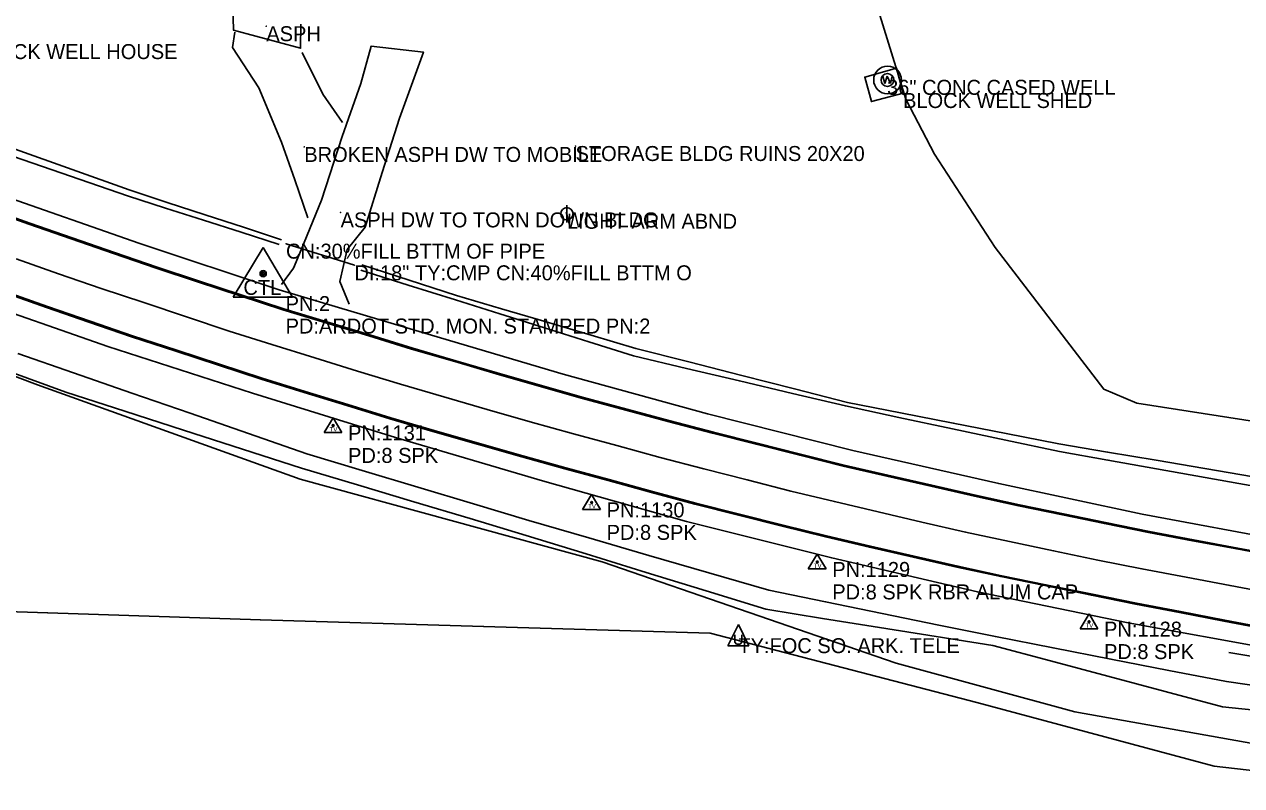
# Model space of a CAD drawing. Extents: x 878399 to 889864, y 1564003 to 1567413.
# Drawn here: x 886065.8 to 886472.5, y 1564453.2 to 1564707.5 of the extents above; entities that cross this region are included whole.
import ezdxf

# ---------------------------------------------------------------- set-up
doc = ezdxf.new("R2010")
doc.units = 0
for name, color, linetype in [('S_BUILDING', 7, 'Continuous'), ('S_BUILDING_ANNOT', 7, 'Continuous'), ('S_DITCHLINE', 7, 'Continuous'), ('S_DRG_PT_SYM', 7, 'Continuous'), ('S_DRIVEWAY', 7, 'Continuous'), ('S_EDGE_BITUMINOUS', 7, 'Continuous'), ('S_EDGE_PAVEMENT', 7, 'Continuous'), ('S_FENCE', 7, 'Continuous'), ('S_FIBER_OPTIC_CABLE', 7, 'Continuous'), ('S_MSC_PT_SYM', 7, 'Continuous'), ('S_PAVEMENT_CROWN', 7, 'Continuous'), ('S_PRIMARY_CTL', 7, 'Continuous'), ('S_PRIMARY_CTL_ANNOT', 7, 'Continuous'), ('S_SECONDARY_CTL', 7, 'Continuous'), ('S_SECONDARY_CTL_ANNOT', 7, 'Continuous'), ('S_SHOULDER', 7, 'Continuous'), ('S_SIDE_DRAIN', 7, 'Continuous'), ('S_SIDE_DRAIN_ANNOT', 7, 'Continuous'), ('S_STR_PT_SYM', 7, 'Continuous'), ('S_SURVEY_TEXT_ANNOT', 7, 'Continuous'), ('S_UTILITY_POLE', 7, 'Continuous'), ('S_UTILITY_POLE_ANNOT', 7, 'Continuous'), ('S_UTL_PT_SYM', 7, 'Continuous'), ('S_WATER_WELL', 7, 'Continuous'), ('S_WATER_WELL_ANNOT', 7, 'Continuous')]:
    doc.layers.add(name, color=color, linetype=linetype)

msp = doc.modelspace()

# ---------------------------------------------------------------- linework, layer by layer
at = {"layer": 'S_BUILDING'}
for p, q in [((886346.55, 1564689.87), (886357.12, 1564692.84)), ((886357.12, 1564692.84), (886359.35, 1564684.57)), ((886348.76, 1564681.74), (886346.55, 1564689.87)), ((886359.35, 1564684.57), (886348.76, 1564681.74))]:
    msp.add_line(p, q, dxfattribs=at)
at = {"layer": 'S_DITCHLINE'}
for points in [[(886151.69, 1564635.57), (886138.96, 1564639.73), (886126.22, 1564643.88), (886113.49, 1564648.04), (886100.75, 1564652.2), (886081.74, 1564659.01), (886062.72, 1564665.83), (886043.71, 1564672.65), (886024.7, 1564679.47), (886007.11, 1564687.39), (885989.52, 1564695.32), (885971.94, 1564703.24), (885954.35, 1564711.17), (885939.66, 1564718.75), (885924.96, 1564726.34), (885905.6, 1564735.73), (885886.23, 1564745.12), (885866.86, 1564754.51), (885847.49, 1564763.9)], [(886150.93, 1564634.01), (886138.26, 1564638.06), (886125.58, 1564642.1), (886112.9, 1564646.14), (886100.22, 1564650.18), (886081.18, 1564656.77), (886062.13, 1564663.36), (886043.09, 1564669.96), (886024.05, 1564676.55), (886006.01, 1564683.98), (885987.98, 1564691.41), (885969.95, 1564698.83), (885951.91, 1564706.26), (885936.25, 1564712.21), (885920.59, 1564718.15), (885901.35, 1564727.33), (885882.11, 1564736.51), (885862.87, 1564745.69), (885843.63, 1564754.86)], [(886476.49, 1564553.26), (886460.26, 1564556.16), (886444.03, 1564559.05), (886427.8, 1564561.95), (886411.56, 1564564.84), (886393.69, 1564568.64), (886375.82, 1564572.44), (886357.95, 1564576.23), (886340.08, 1564580.03), (886322.38, 1564584.21), (886304.67, 1564588.39), (886286.97, 1564592.57), (886269.27, 1564596.75), (886254.4, 1564601.44), (886239.54, 1564606.12), (886224.67, 1564610.81), (886209.8, 1564615.5), (886193.98, 1564620.42), (886178.16, 1564625.35)], [(886476.42, 1564556.37), (886460.17, 1564559.13), (886443.92, 1564561.89), (886427.67, 1564564.66), (886411.42, 1564567.42), (886393.76, 1564570.88), (886376.09, 1564574.34), (886358.43, 1564577.79), (886340.77, 1564581.25), (886323.11, 1564585.76), (886305.44, 1564590.27), (886287.78, 1564594.78), (886270.12, 1564599.29), (886255.14, 1564603.7), (886240.16, 1564608.11), (886225.18, 1564612.52), (886210.2, 1564616.94), (886194.38, 1564622.09), (886178.56, 1564627.24)], [(886481.16, 1564485.98), (886467.4, 1564487.97), (886448.09, 1564491.72), (886428.79, 1564495.48), (886409.48, 1564499.23), (886390.18, 1564502.99), (886371.27, 1564506.86), (886352.36, 1564510.73), (886333.46, 1564514.61), (886314.55, 1564518.48), (886294.5, 1564524.31), (886274.45, 1564530.13), (886254.39, 1564535.95), (886234.34, 1564541.78), (886215.78, 1564547.35), (886197.23, 1564552.92), (886178.67, 1564558.5), (886160.12, 1564564.07), (886140.64, 1564570.83), (886121.16, 1564577.59), (886101.69, 1564584.35), (886082.21, 1564591.11), (886063.62, 1564597.61)], [(886480.05, 1564478.13), (886466.11, 1564479.57), (886446.93, 1564484.67), (886427.74, 1564489.78), (886408.55, 1564494.88), (886389.36, 1564499.99), (886370.4, 1564503.02), (886351.44, 1564506.05), (886332.48, 1564509.08), (886313.52, 1564512.12), (886293.51, 1564518.29), (886273.49, 1564524.46), (886253.48, 1564530.63), (886233.47, 1564536.8), (886214.69, 1564542.42), (886195.9, 1564548.03), (886177.12, 1564553.65), (886158.34, 1564559.27), (886138.67, 1564565.63), (886119, 1564571.99), (886099.33, 1564578.34), (886079.66, 1564584.7), (886061.03, 1564591.49)]]:
    msp.add_lwpolyline(points, dxfattribs=at)
at = {"layer": 'S_DRG_PT_SYM'}
for points in [[(886153.21, 1564634.25), (886153.21, 1564634.3), (886153.21, 1564634.25), (886153.16, 1564634.25), (886153.21, 1564634.25), (886153.21, 1564634.2), (886153.21, 1564634.25), (886153.26, 1564634.25)], [(886176.05, 1564627.02), (886176.05, 1564627.07), (886176.05, 1564627.02), (886176, 1564627.02), (886176.05, 1564627.02), (886176.05, 1564626.97), (886176.05, 1564627.02), (886176.1, 1564627.02)]]:
    msp.add_lwpolyline(points, dxfattribs=at)
at = {"layer": 'S_DRIVEWAY'}
for points in [[(886160.51, 1564642.93), (886156.11, 1564655.57), (886151.7, 1564668.21), (886144.17, 1564686.34), (886135.36, 1564699.78), (886136.06, 1564704.96)], [(886151.65, 1564620.63), (886155.73, 1564626.04), (886158.3, 1564632.14), (886165.07, 1564648.74), (886171.96, 1564670.01), (886178.19, 1564687.72), (886181.69, 1564700.25), (886199.11, 1564698.27), (886191.09, 1564676.16), (886185.35, 1564657.98), (886179.61, 1564639.81), (886173.65, 1564632.28), (886171.15, 1564621.66), (886174.28, 1564614.08)], [(886158.58, 1564698.17), (886165.52, 1564684.23), (886172.07, 1564674.74)]]:
    msp.add_lwpolyline(points, dxfattribs=at)
at = {"layer": 'S_EDGE_BITUMINOUS'}
msp.add_lwpolyline([(886135.38, 1564713.85), (886135.68, 1564705.53), (886158.05, 1564699.54), (886158.15, 1564707.53)], dxfattribs=at)
at = {"layer": 'S_EDGE_PAVEMENT'}
for points in [[(886053.09, 1564645.79), (886067.25, 1564640.82), (886081.41, 1564635.87), (886095.57, 1564630.92), (886109.78, 1564626.1), (886123.61, 1564621.52), (886137.85, 1564616.8), (886137.85, 1564616.8), (886137.85, 1564616.8), (886152.12, 1564612.16), (886166.47, 1564607.79), (886180.82, 1564603.43), (886195.17, 1564599.06), (886209.57, 1564594.85), (886223.37, 1564590.82), (886237.78, 1564586.62), (886252.23, 1564582.58), (886252.23, 1564582.58), (886266.72, 1564578.68), (886281.21, 1564574.77), (886295.7, 1564570.91), (886310.25, 1564567.24), (886324.8, 1564563.58), (886324.8, 1564563.58), (886339.34, 1564559.91), (886339.34, 1564559.91), (886339.34, 1564559.91), (886353.96, 1564556.54), (886368.59, 1564553.22), (886383.22, 1564549.9), (886397.89, 1564546.72), (886412.59, 1564543.68), (886426.62, 1564540.77), (886441.32, 1564537.78), (886456.07, 1564535.02), (886470.81, 1564532.26), (886485.56, 1564529.5)], [(886053.44, 1564646.11), (886067.6, 1564641.14), (886081.76, 1564636.19), (886095.92, 1564631.25), (886110.13, 1564626.43), (886123.96, 1564621.85), (886138.2, 1564617.13), (886138.2, 1564617.13), (886138.2, 1564617.13), (886152.46, 1564612.48), (886166.81, 1564608.12), (886181.17, 1564603.76), (886195.52, 1564599.39), (886209.92, 1564595.17), (886223.71, 1564591.15), (886238.12, 1564586.95), (886252.57, 1564582.91), (886252.57, 1564582.91), (886267.06, 1564579), (886281.54, 1564575.1), (886296.04, 1564571.24), (886310.59, 1564567.57), (886325.13, 1564563.9), (886325.13, 1564563.9), (886339.68, 1564560.24), (886339.68, 1564560.24), (886339.68, 1564560.24), (886354.3, 1564556.87), (886368.93, 1564553.55), (886383.56, 1564550.22), (886398.23, 1564547.05), (886412.93, 1564544.01), (886426.95, 1564541.1), (886441.66, 1564538.11), (886456.4, 1564535.35), (886471.14, 1564532.59), (886485.89, 1564529.83)], [(886059.05, 1564617.92), (886073.21, 1564612.97), (886087.37, 1564608.02), (886087.37, 1564608.02), (886087.37, 1564608.02), (886101.58, 1564603.18), (886116.37, 1564598.34), (886116.37, 1564598.34), (886116.37, 1564598.34), (886130.62, 1564593.66), (886130.62, 1564593.66), (886144.89, 1564589.02), (886144.89, 1564589.02), (886159.22, 1564584.59), (886159.22, 1564584.59), (886173.56, 1564580.17), (886187.89, 1564575.74), (886202.29, 1564571.54), (886217.49, 1564567.2), (886231.93, 1564563.07), (886231.93, 1564563.07), (886246.38, 1564559.03), (886246.38, 1564559.03), (886246.38, 1564559.03), (886260.86, 1564555.09), (886260.86, 1564555.09), (886275.34, 1564551.16), (886289.82, 1564547.25), (886289.82, 1564547.25), (886304.37, 1564543.59), (886318.92, 1564539.94), (886333.47, 1564536.28), (886333.47, 1564536.28), (886333.47, 1564536.28), (886348.08, 1564532.87), (886362.71, 1564529.55), (886377.34, 1564526.22), (886377.34, 1564526.22), (886392, 1564523.02), (886406.71, 1564520.01), (886406.71, 1564520.01), (886422.29, 1564516.83), (886437, 1564513.83), (886437, 1564513.83), (886451.73, 1564511), (886451.73, 1564511), (886466.46, 1564508.17), (886466.46, 1564508.17), (886466.46, 1564508.17), (886481.19, 1564505.34)], [(886059.4, 1564618.25), (886073.56, 1564613.3), (886087.72, 1564608.34), (886087.72, 1564608.34), (886087.72, 1564608.34), (886101.93, 1564603.51), (886116.72, 1564598.66), (886116.72, 1564598.66), (886116.72, 1564598.66), (886130.97, 1564593.99), (886130.97, 1564593.99), (886145.23, 1564589.34), (886145.23, 1564589.34), (886159.57, 1564584.92), (886159.57, 1564584.92), (886173.9, 1564580.49), (886188.23, 1564576.07), (886202.64, 1564571.87), (886217.84, 1564567.53), (886232.27, 1564563.4), (886232.27, 1564563.4), (886246.72, 1564559.35), (886246.72, 1564559.35), (886246.72, 1564559.35), (886261.2, 1564555.42), (886261.2, 1564555.42), (886275.68, 1564551.49), (886290.16, 1564547.58), (886290.16, 1564547.58), (886304.71, 1564543.92), (886319.26, 1564540.27), (886333.81, 1564536.61), (886333.81, 1564536.61), (886333.81, 1564536.61), (886348.42, 1564533.2), (886363.05, 1564529.88), (886377.67, 1564526.55), (886377.67, 1564526.55), (886392.34, 1564523.35), (886407.05, 1564520.34), (886407.05, 1564520.34), (886422.62, 1564517.16), (886437.33, 1564514.16), (886437.33, 1564514.16), (886452.06, 1564511.34), (886452.06, 1564511.34), (886466.79, 1564508.51), (886466.79, 1564508.51), (886466.79, 1564508.51), (886481.52, 1564505.68)]]:
    msp.add_lwpolyline(points, dxfattribs=at)
at = {"layer": 'S_FENCE'}
for p, q in [((886360.27, 1564682.48), (886338.23, 1564753.54)), ((886369.85, 1564664.1), (886360.27, 1564682.48)), ((886390.06, 1564632.95), (886369.85, 1564664.1)), ((886426.44, 1564585.67), (886390.06, 1564632.95)), ((886437.4, 1564581), (886426.44, 1564585.67)), ((886514.17, 1564569.01), (886437.4, 1564581)), ((886073.61, 1564510.98), (886005.69, 1564513.05)), ((886144.63, 1564508.63), (886073.61, 1564510.98)), ((886219.21, 1564506.41), (886144.63, 1564508.63)), ((886294.9, 1564504.19), (886219.21, 1564506.41)), ((886384.02, 1564480.95), (886294.9, 1564504.19)), ((886463.29, 1564459.69), (886384.02, 1564480.95)), ((886520.18, 1564453.2), (886463.29, 1564459.69))]:
    msp.add_line(p, q, dxfattribs=at)
at = {"layer": 'S_FIBER_OPTIC_CABLE'}
for p, q in [((886070.21, 1564587.13), (885957.86, 1564628.9)), ((886157.93, 1564555.63), (886070.21, 1564587.13)), ((886258.85, 1564527.97), (886157.93, 1564555.63)), ((886356.99, 1564494.14), (886258.85, 1564527.97)), ((886416.68, 1564477.84), (886356.99, 1564494.14)), ((886534.49, 1564456.86), (886416.68, 1564477.84))]:
    msp.add_line(p, q, dxfattribs=at)
at = {"layer": 'S_MSC_PT_SYM'}
for points in [[(886146.62, 1564706.9), (886146.62, 1564706.95), (886146.62, 1564706.9), (886146.57, 1564706.9), (886146.62, 1564706.9), (886146.62, 1564706.85), (886146.62, 1564706.9), (886146.67, 1564706.9)], [(886360.27, 1564682.48), (886360.27, 1564682.53), (886360.27, 1564682.48), (886360.22, 1564682.48), (886360.27, 1564682.48), (886360.27, 1564682.43), (886360.27, 1564682.48), (886360.32, 1564682.48)], [(886159.31, 1564666.56), (886159.31, 1564666.61), (886159.31, 1564666.56), (886159.26, 1564666.56), (886159.31, 1564666.56), (886159.31, 1564666.51), (886159.31, 1564666.56), (886159.36, 1564666.56)], [(886249.92, 1564666.87), (886249.92, 1564666.92), (886249.92, 1564666.87), (886249.87, 1564666.87), (886249.92, 1564666.87), (886249.92, 1564666.82), (886249.92, 1564666.87), (886249.97, 1564666.87)], [(886369.85, 1564664.1), (886369.85, 1564664.15), (886369.85, 1564664.1), (886369.8, 1564664.1), (886369.85, 1564664.1), (886369.85, 1564664.05), (886369.85, 1564664.1), (886369.9, 1564664.1)], [(886171.44, 1564644.7), (886171.44, 1564644.75), (886171.44, 1564644.7), (886171.39, 1564644.7), (886171.44, 1564644.7), (886171.44, 1564644.65), (886171.44, 1564644.7), (886171.49, 1564644.7)], [(886390.06, 1564632.95), (886390.06, 1564633), (886390.06, 1564632.95), (886390.01, 1564632.95), (886390.06, 1564632.95), (886390.06, 1564632.9), (886390.06, 1564632.95), (886390.11, 1564632.95)], [(886426.44, 1564585.67), (886426.44, 1564585.72), (886426.44, 1564585.67), (886426.39, 1564585.67), (886426.44, 1564585.67), (886426.44, 1564585.62), (886426.44, 1564585.67), (886426.49, 1564585.67)], [(886437.4, 1564581), (886437.4, 1564581.05), (886437.4, 1564581), (886437.35, 1564581), (886437.4, 1564581), (886437.4, 1564580.95), (886437.4, 1564581), (886437.45, 1564581)], [(886073.61, 1564510.98), (886073.61, 1564511.03), (886073.61, 1564510.98), (886073.56, 1564510.98), (886073.61, 1564510.98), (886073.61, 1564510.93), (886073.61, 1564510.98), (886073.66, 1564510.98)], [(886144.63, 1564508.63), (886144.63, 1564508.68), (886144.63, 1564508.63), (886144.58, 1564508.63), (886144.63, 1564508.63), (886144.63, 1564508.58), (886144.63, 1564508.63), (886144.68, 1564508.63)], [(886219.21, 1564506.41), (886219.21, 1564506.46), (886219.21, 1564506.41), (886219.16, 1564506.41), (886219.21, 1564506.41), (886219.21, 1564506.36), (886219.21, 1564506.41), (886219.26, 1564506.41)], [(886294.9, 1564504.19), (886294.9, 1564504.24), (886294.9, 1564504.19), (886294.85, 1564504.19), (886294.9, 1564504.19), (886294.9, 1564504.14), (886294.9, 1564504.19), (886294.95, 1564504.19)], [(886384.02, 1564480.95), (886384.02, 1564481), (886384.02, 1564480.95), (886383.97, 1564480.95), (886384.02, 1564480.95), (886384.02, 1564480.9), (886384.02, 1564480.95), (886384.07, 1564480.95)], [(886463.29, 1564459.69), (886463.29, 1564459.74), (886463.29, 1564459.69), (886463.24, 1564459.69), (886463.29, 1564459.69), (886463.29, 1564459.64), (886463.29, 1564459.69), (886463.34, 1564459.69)]]:
    msp.add_lwpolyline(points, dxfattribs=at)
at = {"layer": 'S_PAVEMENT_CROWN'}
msp.add_lwpolyline([(886063.1, 1564629.23), (886077.25, 1564624.23), (886091.41, 1564619.3), (886105.65, 1564614.56), (886119.95, 1564609.79), (886134.18, 1564605.05), (886134.18, 1564605.05), (886148.49, 1564600.56), (886162.81, 1564596.08), (886177.13, 1564591.61), (886191.5, 1564587.29), (886205.9, 1564583.08), (886220.39, 1564578.84), (886234.81, 1564574.69), (886249.29, 1564570.73), (886263.76, 1564566.78), (886278.24, 1564562.82), (886292.76, 1564559.08), (886307.3, 1564555.35), (886321.83, 1564551.63), (886336.4, 1564548.09), (886351.01, 1564544.67), (886365.62, 1564541.25), (886380.25, 1564537.9), (886380.25, 1564537.9), (886380.25, 1564537.9), (886394.93, 1564534.78), (886409.61, 1564531.67), (886409.61, 1564531.67), (886409.61, 1564531.67), (886424.41, 1564528.52), (886439.13, 1564525.67), (886439.13, 1564525.67), (886453.87, 1564522.84), (886468.6, 1564520.01), (886483.36, 1564517.33)], dxfattribs=at)
at = {"layer": 'S_PRIMARY_CTL'}
for p, q in [((886145.57, 1564632.94), (886135.53, 1564616.42)), ((886145.57, 1564632.94), (886155.39, 1564616.42)), ((886135.53, 1564616.42), (886155.39, 1564616.42))]:
    msp.add_line(p, q, dxfattribs=at)
for radius in [1.04, 0.609, 0.344]:
    msp.add_circle((886145.57, 1564624.24), radius, dxfattribs=at)
at = {"layer": 'S_SECONDARY_CTL'}
for p, q in [((886168.93, 1564576.13), (886165.92, 1564571.18)), ((886168.93, 1564576.13), (886171.88, 1564571.18)), ((886165.92, 1564571.18), (886171.88, 1564571.18)), ((886255.31, 1564550.43), (886252.3, 1564545.48)), ((886255.31, 1564550.43), (886258.26, 1564545.48)), ((886252.3, 1564545.48), (886258.26, 1564545.48)), ((886330.69, 1564530.53), (886327.68, 1564525.58)), ((886330.69, 1564530.53), (886333.64, 1564525.58)), ((886327.68, 1564525.58), (886333.64, 1564525.58)), ((886421.47, 1564510.59), (886418.46, 1564505.64)), ((886421.47, 1564510.59), (886424.41, 1564505.64)), ((886418.46, 1564505.64), (886424.41, 1564505.64))]:
    msp.add_line(p, q, dxfattribs=at)
for centre, radius in [((886168.93, 1564573.52), 0.311), ((886168.93, 1564573.52), 0.183), ((886168.93, 1564573.52), 0.103), ((886255.31, 1564547.82), 0.311), ((886255.31, 1564547.82), 0.183), ((886255.31, 1564547.82), 0.103), ((886330.69, 1564527.92), 0.311), ((886330.69, 1564527.92), 0.183), ((886330.69, 1564527.92), 0.103), ((886421.47, 1564507.98), 0.311), ((886421.47, 1564507.98), 0.183), ((886421.47, 1564507.98), 0.103)]:
    msp.add_circle(centre, radius, dxfattribs=at)
at = {"layer": 'S_SHOULDER'}
for points in [[(885477.34, 1564934.42), (885519.82, 1564908.04), (885562.37, 1564882.88), (885605.78, 1564858.06), (885649.01, 1564834.13), (885693.1, 1564810.55), (885737.12, 1564788.02), (885781.98, 1564765.92), (885827.15, 1564744.48), (885871.93, 1564724.36), (885917.84, 1564704.55), (885964.25, 1564685.89), (886009.9, 1564668.12), (886056.86, 1564650.94), (886104.07, 1564634.45), (886150.87, 1564618.86), (886198.78, 1564604.53), (886245.81, 1564590.69), (886294.03, 1564577.4), (886342.52, 1564565.18), (886391.29, 1564554.1), (886439.19, 1564543.9), (886488.35, 1564534.77)], [(885502.12, 1564876.69), (885545.5, 1564850.36), (885589.04, 1564825.78), (885633.6, 1564801.51), (885677.62, 1564777.79), (885722.81, 1564754.83), (885767.3, 1564732.01), (885812.49, 1564710.58), (885858.95, 1564689.25), (885905.17, 1564670.16), (885951.57, 1564651.51), (885999.47, 1564633.52), (886046.46, 1564616.42), (886093.66, 1564599.92), (886142, 1564584.31), (886189.76, 1564569.49), (886238.85, 1564555.08), (886286.99, 1564541.47), (886335.49, 1564529.28), (886384.19, 1564517.92), (886434.5, 1564507.62), (886483.69, 1564498.68)], [(886482.28, 1564495.37), (886468.19, 1564497.69)]]:
    msp.add_lwpolyline(points, dxfattribs=at)
at = {"layer": 'S_SIDE_DRAIN'}
msp.add_line((886176.05, 1564627.02), (886153.21, 1564634.25), dxfattribs=at)
at = {"layer": 'S_STR_PT_SYM'}
for points in [[(886357.12, 1564692.84), (886357.12, 1564692.89), (886357.12, 1564692.84), (886357.07, 1564692.84), (886357.12, 1564692.84), (886357.12, 1564692.79), (886357.12, 1564692.84), (886357.17, 1564692.84)], [(886346.55, 1564689.87), (886346.55, 1564689.92), (886346.55, 1564689.87), (886346.5, 1564689.87), (886346.55, 1564689.87), (886346.55, 1564689.82), (886346.55, 1564689.87), (886346.6, 1564689.87)], [(886359.35, 1564684.57), (886359.35, 1564684.62), (886359.35, 1564684.57), (886359.3, 1564684.57), (886359.35, 1564684.57), (886359.35, 1564684.52), (886359.35, 1564684.57), (886359.4, 1564684.57)], [(886348.76, 1564681.74), (886348.76, 1564681.79), (886348.76, 1564681.74), (886348.71, 1564681.74), (886348.76, 1564681.74), (886348.76, 1564681.69), (886348.76, 1564681.74), (886348.81, 1564681.74)]]:
    msp.add_lwpolyline(points, dxfattribs=at)
at = {"layer": 'S_UTILITY_POLE'}
for p, q in [((886247.05, 1564641.31), (886247.05, 1564647.09)), ((886304.33, 1564507), (886300.8, 1564499.91)), ((886303.12, 1564501.15), (886303.12, 1564503.59)), ((886304.33, 1564507), (886307.81, 1564499.91)), ((886305.49, 1564503.59), (886305.49, 1564501.15)), ((886300.8, 1564499.91), (886307.81, 1564499.91)), ((886303.74, 1564500.49), (886303.12, 1564501.15)), ((886304.95, 1564500.49), (886303.74, 1564500.49)), ((886305.49, 1564501.15), (886304.95, 1564500.49))]:
    msp.add_line(p, q, dxfattribs=at)
msp.add_circle((886247.05, 1564644.24), 2.05, dxfattribs=at)
at = {"layer": 'S_UTL_PT_SYM'}
for points in [[(886070.21, 1564587.13), (886070.21, 1564587.18), (886070.21, 1564587.13), (886070.16, 1564587.13), (886070.21, 1564587.13), (886070.21, 1564587.08), (886070.21, 1564587.13), (886070.26, 1564587.13)], [(886157.93, 1564555.63), (886157.93, 1564555.68), (886157.93, 1564555.63), (886157.88, 1564555.63), (886157.93, 1564555.63), (886157.93, 1564555.58), (886157.93, 1564555.63), (886157.98, 1564555.63)], [(886258.85, 1564527.97), (886258.85, 1564528.02), (886258.85, 1564527.97), (886258.8, 1564527.97), (886258.85, 1564527.97), (886258.85, 1564527.92), (886258.85, 1564527.97), (886258.9, 1564527.97)], [(886356.99, 1564494.14), (886356.99, 1564494.19), (886356.99, 1564494.14), (886356.94, 1564494.14), (886356.99, 1564494.14), (886356.99, 1564494.09), (886356.99, 1564494.14), (886357.04, 1564494.14)], [(886416.68, 1564477.84), (886416.68, 1564477.89), (886416.68, 1564477.84), (886416.63, 1564477.84), (886416.68, 1564477.84), (886416.68, 1564477.79), (886416.68, 1564477.84), (886416.73, 1564477.84)]]:
    msp.add_lwpolyline(points, dxfattribs=at)
at = {"layer": 'S_WATER_WELL'}
for p, q in [((886352.6, 1564690.2), (886353.26, 1564687.72)), ((886353.26, 1564687.72), (886354.07, 1564690.2)), ((886354.07, 1564690.2), (886355.12, 1564687.72)), ((886355.12, 1564687.72), (886355.7, 1564690.24))]:
    msp.add_line(p, q, dxfattribs=at)
for centre, radius in [((886354.16, 1564688.95), 4.63), ((886354.13, 1564688.94), 2.13)]:
    msp.add_circle(centre, radius, dxfattribs=at)

# ---------------------------------------------------------------- texts
at = {"layer": 'S_BUILDING_ANNOT'}
msp.add_text('BLOCK WELL SHED', height=5, dxfattribs=at).set_placement((886359.35, 1564679.57))
at = {"layer": 'S_PRIMARY_CTL'}
msp.add_text('CTL', height=5, rotation=360, dxfattribs=at).set_placement((886138.98, 1564617.16))
at = {"layer": 'S_PRIMARY_CTL_ANNOT'}
for s, p in [('PN:2', (886153.07, 1564611.74)), ('PD:ARDOT STD. MON. STAMPED PN:2', (886153.07, 1564604.24))]:
    msp.add_text(s, height=5, dxfattribs=at).set_placement(p)
at = {"layer": 'S_SECONDARY_CTL'}
for p in [(886167.73, 1564571.51), (886254.11, 1564545.81), (886329.49, 1564525.91), (886420.26, 1564505.97)]:
    msp.add_text('TV', height=1.5, rotation=360, dxfattribs=at).set_placement(p)
at = {"layer": 'S_SECONDARY_CTL_ANNOT'}
for s, p in [('PN:1131', (886173.93, 1564568.52)), ('PD:8 SPK', (886173.93, 1564561.02)), ('PN:1130', (886260.31, 1564542.82)), ('PD:8 SPK', (886260.31, 1564535.32)), ('PN:1129', (886335.69, 1564522.92)), ('PD:8 SPK RBR ALUM CAP', (886335.69, 1564515.42)), ('PN:1128', (886426.47, 1564502.98)), ('PD:8 SPK', (886426.47, 1564495.48))]:
    msp.add_text(s, height=5, dxfattribs=at).set_placement(p)
at = {"layer": 'S_SIDE_DRAIN_ANNOT'}
for s, p in [('CN:30%FILL BTTM OF PIPE', (886153.21, 1564629.25)), ('DI:18" TY:CMP CN:40%FILL BTTM O', (886176.05, 1564622.02))]:
    msp.add_text(s, height=5, dxfattribs=at).set_placement(p)
at = {"layer": 'S_SURVEY_TEXT_ANNOT'}
for s, p in [('ASPH', (886146.62, 1564701.9)), ('BLOCK WELL HOUSE', (886048.58, 1564695.92)), ('BROKEN ASPH DW TO MOBILE', (886159.31, 1564661.56)), ('STORAGE BLDG RUINS 20X20', (886249.92, 1564661.87)), ('ASPH DW TO TORN DOWN BLDG', (886171.44, 1564639.7))]:
    msp.add_text(s, height=5, dxfattribs=at).set_placement(p)
at = {"layer": 'S_UTILITY_POLE_ANNOT'}
for s, p in [('LIGHT ARM ABND', (886247.05, 1564639.24)), ('TY:FOC SO. ARK. TELE', (886304.33, 1564497.47))]:
    msp.add_text(s, height=5, dxfattribs=at).set_placement(p)
at = {"layer": 'S_WATER_WELL_ANNOT'}
msp.add_text('36" CONC CASED WELL', height=5, dxfattribs=at).set_placement((886354.01, 1564683.98))

doc.saveas('drawing.dxf')
